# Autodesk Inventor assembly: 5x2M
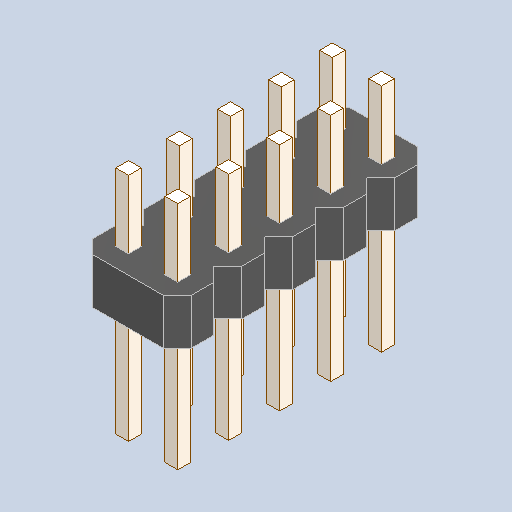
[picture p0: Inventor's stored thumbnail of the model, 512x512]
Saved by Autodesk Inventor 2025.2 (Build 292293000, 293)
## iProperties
Created: 2025-04
Part Number: 5x2M
Description: PART--DESC
Document SubType Name: Assembly
Designer: BennF
Author: BennF
Revision Number: NONE
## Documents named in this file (3)
- C:\Users\BennF\Nextcloud\Benutzer\CNC JarBeRi\existing parts\Electronics\RepRap A4988 Shied (USE WITHOUT ARDUINO)\reprap-a4988-1.snapshot.1\RepRap\RepRap\5x2M.iam
- C:\Users\BennF\Nextcloud\Benutzer\CNC JarBeRi\existing parts\Electronics\RepRap A4988 Shied (USE WITHOUT ARDUINO)\reprap-a4988-1.snapshot.1\RepRap\RepRap\5x2M Geometry.ipt
- C:\Users\BennF\Nextcloud\Benutzer\CNC JarBeRi\existing parts\Electronics\RepRap A4988 Shied (USE WITHOUT ARDUINO)\reprap-a4988-1.snapshot.1\RepRap\RepRap\pin9.ipt
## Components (2 placed, 2 different names)
1. 5x2M Geometry
2. pin9
